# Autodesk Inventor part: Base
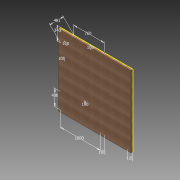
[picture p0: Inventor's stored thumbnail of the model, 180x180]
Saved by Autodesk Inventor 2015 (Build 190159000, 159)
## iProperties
Created: 2015-04
Part Number: Base
Material: Wood (Birch)
Document SubType Name: Modeling
Designer: suporte
Density: 0.55 g/cm^3
Appearance: Birch - Natural Polished
Author: suporte
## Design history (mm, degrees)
sketch "Sketch1"
  geometry: L1 (912.5, 900)-(-912.5, 900); L2 (-912.5, 900)-(-912.5, -900); L3 (-912.5, -900)-(912.5, -900); L4 (912.5, -900)-(912.5, 900); L5 (912.5, 900)-(-912.5, -900); L6 (-912.5, 900)-(912.5, -900); 1 further point
  constraints: 12 end point, 2 midpoint, 2 parallel, 1 horizontal, 1 perpendicular
  dimensions: "d0" = 1825 distance of L2.end L3.end; "d1" = 1800 distance of L1.end L2.end
extrude "Extrusion1" new body sketch "Sketch1" distance "d2" = 50; taper "d3" = 0 deg
sketch "Sketch2"
  geometry: L1 (-572.263, -900)-(-912.5, -560); L2 (-912.5, 900)-(-912.5, -900) reference; L3 (-912.5, 500)-(87.5, 500); L4 (87.5, 500)-(87.5, 900); L5 (-912.5, -900)-(912.5, -900) reference; L6 (787.5, -900)-(787.5, 900); L7 (187.737, -900)-(187.737, -800); L8 (187.737, -800)-(-530.862, -800); L9 (-530.862, -800)-(-812.5, -518.558); L10 (-812.5, -518.558)-(-812.5, 400); L11 (-812.5, 400)-(187.5, 400); L12 (187.5, 400)-(187.5, 900); L13 (912.5, 900)-(-912.5, 900) reference; L14 (912.5, -900)-(912.5, 900) reference; 1 further point
  constraints: 20 end point, 8 point on line, 4 perpendicular, 3 vertical, 1 horizontal, 1 parallel
  dimensions: "d5" = 1000 distance between parallel lines of L2 L4; "d6" = 100 distance between parallel lines of L4 L12; "d7" = 100 distance between parallel lines of L3 L11; "d8" = 100 distance between parallel lines of L5 L8; "d9" = 481 distance of L1.start L1.end; "d10" = 100 distance between parallel lines of L2 L10; "d11" = 400 distance between parallel lines of L13 L3; "d12" = 340 distance from line of L5 L1.end; "d13" = 760 distance from line of L1.start L7; "d14" = 100 distance between parallel lines of L1 L9; "d15" = 125 distance between parallel lines of L14 L6
body "Solid1"
